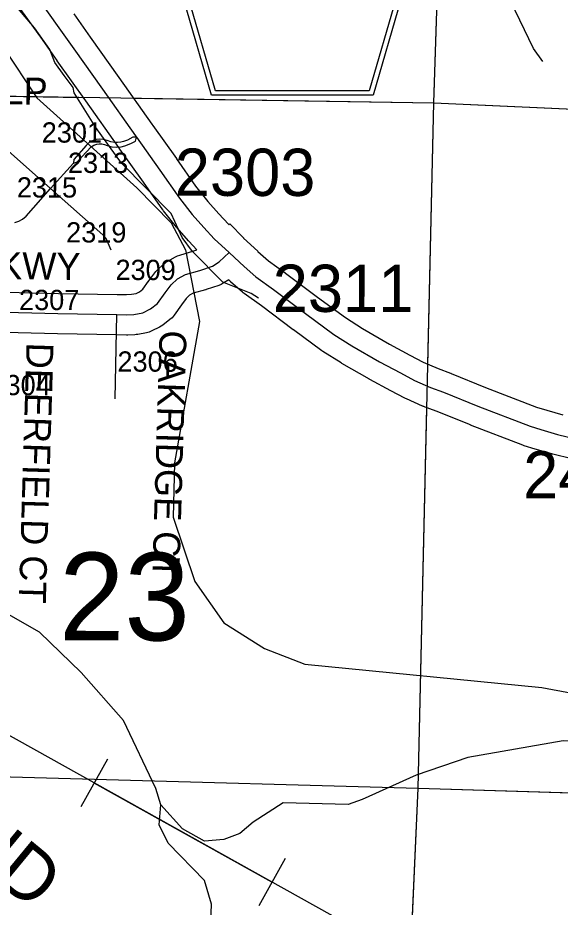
# Model space of a CAD drawing. Extents: x -132.8 to -73.3, y -60 to -26.
# Drawn here: x -117.648 to -116.845, y -54.589 to -53.272 of the extents above; entities that cross this region are included whole.
import ezdxf

# ---------------------------------------------------------------- set-up
doc = ezdxf.new("R2010")
doc.units = 0
for name, color, linetype in [('tdCoDivCarto', 7, 'Continuous'), ('tdCoHydroRiver', 7, 'Continuous'), ('tdCoPipe', 7, 'Continuous'), ('tdCoRRCL', 7, 'Continuous'), ('tdCoSecDivCarto', 7, 'Continuous'), ('tdCoSecRdNmbr', 7, 'Continuous'), ('tdCoSecRdTxt', 7, 'Continuous'), ('tdCoSecRteBand', 7, 'Continuous'), ('tdCoSecRteCL', 7, 'Continuous'), ('tdCoSectLine', 7, 'Continuous'), ('tdCoSectLinePart', 7, 'Continuous'), ('tdCoSectNmbr', 7, 'Continuous'), ('tdCoShieldCoRteHrd', 7, 'Continuous'), ('tdCoSurfAsphalt', 7, 'Continuous'), ('tdCoSurfConc', 7, 'Continuous'), ('tdCoSurfConcUnbanded', 7, 'Continuous')]:
    doc.layers.add(name, color=color, linetype=linetype)

msp = doc.modelspace()

# ---------------------------------------------------------------- linework, layer by layer
at = {"layer": 'tdCoDivCarto'}
for p, q in [((-117.5658, -53.4871), (-117.5657, -53.4871)), ((-117.5657, -53.4871), (-117.5654, -53.487))]:
    msp.add_line(p, q, dxfattribs=at)
for points in [[(-117.4725, -53.4488), (-117.4776, -53.4485), (-117.4858, -53.453), (-117.4916, -53.4551), (-117.4956, -53.456), (-117.5003, -53.4564), (-117.5051, -53.4564), (-117.5105, -53.4554), (-117.5157, -53.4535), (-117.5212, -53.452), (-117.5273, -53.4516), (-117.5319, -53.4522), (-117.5366, -53.4535), (-117.5418, -53.456), (-117.5471, -53.4608), (-117.5651, -53.4816), (-117.5658, -53.4871)], [(-117.5654, -53.487), (-117.5604, -53.4853), (-117.5396, -53.4629), (-117.5354, -53.4604), (-117.5311, -53.4588), (-117.5276, -53.4583), (-117.5235, -53.4586), (-117.5198, -53.4595), (-117.5157, -53.4609), (-117.5089, -53.4627), (-117.5022, -53.4632), (-117.4949, -53.4628), (-117.4895, -53.4616), (-117.4808, -53.4582), (-117.4739, -53.4543), (-117.4725, -53.4488)]]:
    msp.add_lwpolyline(points, dxfattribs=at)
at = {"layer": 'tdCoHydroRiver'}
for points in [[(-116.8707, -53.3366), (-116.8844, -53.3173), (-116.9249, -53.2327)], [(-117.2918, -53.6868), (-117.3027, -53.6802), (-117.3448, -53.6633), (-117.3894, -53.6179), (-117.4046, -53.597), (-117.421, -53.5618), (-117.4948, -53.4873), (-117.5328, -53.4342), (-117.5646, -53.3828), (-117.566, -53.3749), (-117.5797, -53.3572), (-117.5934, -53.3379), (-117.6008, -53.3188), (-117.6236, -53.2866), (-117.6481, -53.2575)], [(-117.4366, -54.4371), (-117.4438, -54.4133), (-117.4916, -54.3126), (-117.5545, -54.2414), (-117.616, -54.1814), (-117.6689, -54.1516), (-117.8063, -54.0974), (-117.9586, -54.0665), (-118.0751, -54.0539), (-118.1447, -54.0599), (-118.244, -54.114), (-118.2987, -54.152), (-118.3739, -54.1894), (-118.4117, -54.1884), (-118.4729, -54.1741), (-118.557, -54.1892), (-118.5885, -54.1868), (-118.6135, -54.1798), (-118.6484, -54.1836), (-118.6691, -54.1925), (-118.7064, -54.2294), (-118.8548, -54.2285)], [(-116.6489, -54.5492), (-116.6502, -54.5382), (-116.6548, -54.5349), (-116.6677, -54.4809), (-116.6997, -54.4359), (-116.7766, -54.3582), (-116.8062, -54.3433), (-116.8409, -54.3424), (-116.982, -54.3672), (-117.0585, -54.3936), (-117.1383, -54.4295), (-117.159, -54.4368), (-117.2551, -54.4342)], [(-117.2551, -54.4342), (-117.2999, -54.4629), (-117.3193, -54.4797), (-117.3432, -54.4885), (-117.3717, -54.4909), (-117.4044, -54.4727), (-117.4366, -54.4371)], [(-117.3094, -55.4046), (-117.3381, -55.3565), (-117.3421, -55.3296), (-117.3396, -55.2949), (-117.3343, -55.2745), (-117.3292, -55.2021), (-117.3362, -55.1672), (-117.3422, -55.156), (-117.3509, -55.1289), (-117.3498, -55.0296), (-117.3542, -55.0168), (-117.3624, -54.9093), (-117.3589, -54.6601), (-117.3627, -54.6253), (-117.3616, -54.5843), (-117.3717, -54.5493), (-117.4255, -54.4942), (-117.439, -54.467), (-117.4366, -54.4371)]]:
    msp.add_lwpolyline(points, dxfattribs=at)
at = {"layer": 'tdCoPipe'}
for p, q in [((-117.5153, -54.3699), (-117.5546, -54.4403)), ((-117.2521, -54.5167), (-117.2913, -54.587))]:
    msp.add_line(p, q, dxfattribs=at)
for points in [[(-115.7327, -56.7093), (-116.3792, -55.5939), (-116.7637, -54.8353), (-118.1151, -54.0815), (-118.6092, -53.8056), (-119.7966, -53.496), (-120.031, -53.2709)], [(-117.2718, -54.5519), (-117.535, -54.4051)]]:
    msp.add_lwpolyline(points, dxfattribs=at)
at = {"layer": 'tdCoRRCL'}
msp.add_lwpolyline([(-117.7743, -53.0804), (-117.6699, -53.3151), (-117.6198, -53.3905), (-117.4718, -53.5238), (-117.421, -53.5756), (-117.4, -53.6156), (-117.379, -53.7218), (-117.416, -53.9307), (-117.4181, -54.0111), (-117.3859, -54.1067), (-117.3433, -54.1677), (-117.2827, -54.2056), (-117.2233, -54.2292), (-116.8722, -54.2637), (-116.7827, -54.2802), (-116.7328, -54.3036), (-116.6616, -54.3591), (-116.6342, -54.3961), (-116.621, -54.4343), (-116.6103, -54.5119)], dxfattribs=at)
at = {"layer": 'tdCoSecDivCarto'}
for p, q in [((-117.4776, -53.4485), (-117.4858, -53.453)), ((-117.4725, -53.4488), (-117.4776, -53.4485)), ((-117.4739, -53.4543), (-117.4725, -53.4488)), ((-117.5471, -53.4608), (-117.5651, -53.4816)), ((-117.5418, -53.456), (-117.5471, -53.4608)), ((-117.5366, -53.4535), (-117.5418, -53.456)), ((-117.5396, -53.4629), (-117.5354, -53.4604)), ((-117.5319, -53.4522), (-117.5366, -53.4535)), ((-117.5354, -53.4604), (-117.5311, -53.4588)), ((-117.5273, -53.4516), (-117.5319, -53.4522)), ((-117.5311, -53.4588), (-117.5276, -53.4583)), ((-117.5276, -53.4583), (-117.5235, -53.4586)), ((-117.5212, -53.452), (-117.5273, -53.4516)), ((-117.5235, -53.4586), (-117.5198, -53.4595)), ((-117.5157, -53.4535), (-117.5212, -53.452)), ((-117.5198, -53.4595), (-117.5157, -53.4609)), ((-117.5105, -53.4554), (-117.5157, -53.4535)), ((-117.5157, -53.4609), (-117.5089, -53.4627)), ((-117.5051, -53.4564), (-117.5105, -53.4554)), ((-117.5003, -53.4564), (-117.5051, -53.4564)), ((-117.4956, -53.456), (-117.5003, -53.4564)), ((-117.4916, -53.4551), (-117.4956, -53.456)), ((-117.4949, -53.4628), (-117.4895, -53.4616)), ((-117.4858, -53.453), (-117.4916, -53.4551)), ((-117.4895, -53.4616), (-117.4808, -53.4582)), ((-117.4808, -53.4582), (-117.4739, -53.4543)), ((-117.5604, -53.4853), (-117.5396, -53.4629)), ((-117.5089, -53.4627), (-117.5022, -53.4632)), ((-117.5022, -53.4632), (-117.4949, -53.4628)), ((-117.5651, -53.4816), (-117.5658, -53.4871)), ((-117.5658, -53.4871), (-117.5657, -53.4871)), ((-117.5657, -53.4871), (-117.5654, -53.487)), ((-117.5654, -53.487), (-117.5604, -53.4853))]:
    msp.add_line(p, q, dxfattribs=at)
at = {"layer": 'tdCoSecRteBand'}
for points in [[(-117.6855, -53.6774), (-117.588, -53.6799), (-117.501, -53.6814), (-117.4872, -53.6816), (-117.4797, -53.6813), (-117.4728, -53.68), (-117.4678, -53.6775), (-117.463, -53.6738), (-117.4545, -53.6619), (-117.4543, -53.6616), (-117.4541, -53.6613), (-117.4452, -53.6495), (-117.4437, -53.6475), (-117.4419, -53.6457), (-117.4322, -53.6366), (-117.4295, -53.634), (-117.4261, -53.6321), (-117.4145, -53.6257), (-117.4116, -53.6241), (-117.4084, -53.6232), (-117.3877, -53.6171), (-117.3829, -53.6156), (-117.3948, -53.6027), (-117.395, -53.6025), (-117.3952, -53.6023), (-117.4123, -53.5829), (-117.4128, -53.5823), (-117.4133, -53.5817), (-117.4324, -53.5577), (-117.433, -53.5569), (-117.4335, -53.5562), (-117.4622, -53.515), (-117.4969, -53.4662), (-117.4984, -53.464), (-117.4985, -53.464), (-117.4985, -53.464), (-117.5474, -53.3948), (-117.5898, -53.3355), (-117.5899, -53.3353), (-117.59, -53.3352), (-117.6142, -53.3004), (-117.6603, -53.2358)], [(-117.5651, -53.266), (-117.5409, -53.3007), (-117.4985, -53.36), (-117.4984, -53.3601), (-117.4984, -53.3601), (-117.4495, -53.4293), (-117.448, -53.4314), (-117.4133, -53.4804), (-117.4132, -53.4805), (-117.4131, -53.4806), (-117.3848, -53.5211), (-117.3668, -53.5438), (-117.3504, -53.5623), (-117.3364, -53.5776), (-117.3356, -53.5783), (-117.3341, -53.5769), (-117.3142, -53.5979), (-117.3141, -53.598), (-117.3141, -53.598), (-117.2928, -53.6174), (-117.2931, -53.6177), (-117.293, -53.6178), (-117.277, -53.6319), (-117.2522, -53.6497), (-117.2519, -53.6499), (-117.2516, -53.6501), (-117.2045, -53.6857), (-117.1631, -53.7158), (-117.1378, -53.7321), (-117.098, -53.755), (-117.0676, -53.7713), (-117.0479, -53.7817), (-117.0257, -53.7914), (-117.0075, -53.7981), (-117.0071, -53.7983), (-117.0067, -53.7985), (-116.9558, -53.8191), (-116.88, -53.8485), (-116.8651, -53.8529), (-116.8412, -53.86)], [(-116.8278, -53.9251), (-116.8562, -53.9181), (-116.8568, -53.9179), (-116.8575, -53.9177), (-116.8822, -53.9105), (-116.8823, -53.9104), (-116.8824, -53.9104), (-116.8984, -53.9056), (-116.8995, -53.9052), (-116.9006, -53.9048), (-116.9777, -53.8749), (-116.9779, -53.8748), (-116.9781, -53.8748), (-117.0288, -53.8542), (-117.0474, -53.8474), (-117.0482, -53.8471), (-117.049, -53.8467), (-117.0729, -53.8362), (-117.074, -53.8358), (-117.0749, -53.8353), (-117.0957, -53.8243), (-117.0958, -53.8242), (-117.0959, -53.8242), (-117.1268, -53.8076), (-117.1272, -53.8074), (-117.1275, -53.8072), (-117.1683, -53.7837), (-117.169, -53.7834), (-117.1696, -53.783), (-117.1963, -53.7659), (-117.197, -53.7654), (-117.1978, -53.7649), (-117.2401, -53.734), (-117.2403, -53.7339), (-117.2405, -53.7337), (-117.2874, -53.6982), (-117.3131, -53.6799), (-117.3143, -53.679), (-117.3154, -53.678), (-117.333, -53.6626), (-117.3334, -53.6622), (-117.3338, -53.6619), (-117.3359, -53.6599), (-117.344, -53.665), (-117.3471, -53.667), (-117.3507, -53.6681), (-117.3694, -53.6743), (-117.3699, -53.6745), (-117.3704, -53.6746), (-117.3884, -53.6798), (-117.3937, -53.6828), (-117.3987, -53.6875), (-117.4059, -53.6971), (-117.4168, -53.7123), (-117.4194, -53.716), (-117.4229, -53.7187), (-117.4335, -53.7268), (-117.4358, -53.7286), (-117.4384, -53.7299), (-117.4497, -53.7355), (-117.4535, -53.7374), (-117.4576, -53.7382), (-117.4706, -53.7406), (-117.4727, -53.741), (-117.4748, -53.7411), (-117.4854, -53.7416), (-117.4864, -53.7417), (-117.4873, -53.7416), (-117.502, -53.7414), (-117.5892, -53.7399), (-117.5893, -53.7399), (-117.5894, -53.7399), (-117.687, -53.7374)]]:
    msp.add_lwpolyline(points, dxfattribs=at)
at = {"layer": 'tdCoSecRteCL'}
for p, q in [((-117.5995, -53.5245), (-117.5658, -53.4871)), ((-117.504, -53.8362), (-117.5015, -53.7114))]:
    msp.add_line(p, q, dxfattribs=at)
for points in [[(-118.338, -52.7262), (-118.2743, -52.753), (-118.2436, -52.7666), (-118.1841, -52.7924), (-118.1223, -52.8219), (-118.069, -52.8495), (-118.0022, -52.8856), (-117.937, -52.9205), (-117.8789, -52.9515), (-117.842, -52.9712), (-117.822, -52.9834), (-117.8084, -52.993), (-117.7978, -53.002), (-117.7849, -53.0143), (-117.7727, -53.029), (-117.7529, -53.0555), (-117.7258, -53.0929), (-117.69, -53.1429), (-117.6359, -53.2183), (-117.5897, -53.2831), (-117.5654, -53.318), (-117.5229, -53.3774), (-117.474, -53.4467), (-117.4725, -53.4488)], [(-117.4725, -53.4488), (-117.4776, -53.4485), (-117.4858, -53.453), (-117.4916, -53.4551), (-117.4956, -53.456), (-117.5003, -53.4564), (-117.5051, -53.4564), (-117.5105, -53.4554), (-117.5157, -53.4535), (-117.5212, -53.452), (-117.5273, -53.4516), (-117.5319, -53.4522), (-117.5366, -53.4535), (-117.5418, -53.456), (-117.5471, -53.4608), (-117.5651, -53.4816), (-117.5658, -53.4871)], [(-117.5658, -53.4871), (-117.5657, -53.4871), (-117.5654, -53.487), (-117.5604, -53.4853), (-117.5396, -53.4629), (-117.5354, -53.4604), (-117.5311, -53.4588), (-117.5276, -53.4583), (-117.5235, -53.4586), (-117.5198, -53.4595), (-117.5157, -53.4609), (-117.5089, -53.4627), (-117.5022, -53.4632), (-117.4949, -53.4628), (-117.4895, -53.4616), (-117.4808, -53.4582), (-117.4739, -53.4543), (-117.4725, -53.4488)], [(-117.4725, -53.4488), (-117.4377, -53.4977), (-117.4089, -53.539), (-117.3898, -53.5631), (-117.3727, -53.5824), (-117.3576, -53.5989), (-117.3352, -53.6193)], [(-117.5995, -53.5245), (-117.6668, -53.465)], [(-117.6526, -53.5751), (-117.6467, -53.5729), (-117.6412, -53.57), (-117.6357, -53.5655), (-117.5995, -53.5245)], [(-117.5098, -53.6157), (-117.5173, -53.5987), (-117.5223, -53.593), (-117.5995, -53.5245)], [(-117.5015, -53.7114), (-117.4868, -53.7117), (-117.4762, -53.7112), (-117.4631, -53.7087), (-117.4518, -53.703), (-117.4412, -53.6949), (-117.4301, -53.6793), (-117.4212, -53.6675), (-117.4116, -53.6584), (-117.4, -53.652), (-117.3788, -53.6458), (-117.3601, -53.6396), (-117.3499, -53.6332), (-117.3352, -53.6193)], [(-117.3352, -53.6193), (-117.3345, -53.6199), (-117.3132, -53.64), (-117.2956, -53.6555), (-117.2697, -53.6741), (-117.2224, -53.7098), (-117.1801, -53.7406), (-117.1534, -53.7577), (-117.1126, -53.7812), (-117.0817, -53.7978), (-117.0609, -53.8088), (-117.037, -53.8192), (-117.0179, -53.8263), (-116.9668, -53.8469), (-116.8898, -53.8768), (-116.8737, -53.8817), (-116.849, -53.889), (-116.8206, -53.896)], [(-117.6863, -53.7074), (-117.5887, -53.7099), (-117.5015, -53.7114)]]:
    msp.add_lwpolyline(points, dxfattribs=at)
at = {"layer": 'tdCoSectLine'}
for points in [[(-117.0322, -53.3979), (-116.9995, -52.4001)], [(-118.0219, -53.382), (-117.0322, -53.3979)], [(-117.0554, -54.4124), (-117.0322, -53.3979)], [(-117.0322, -53.3979), (-116.042, -53.4425)], [(-118.0496, -54.385), (-117.0554, -54.4124)], [(-117.0994, -55.4066), (-117.0554, -54.4124)], [(-117.0554, -54.4124), (-116.0724, -54.4424)]]:
    msp.add_lwpolyline(points, dxfattribs=at)
at = {"layer": 'tdCoSectLinePart'}
for points in [[(-117.0322, -53.3979), (-117.0004, -52.4272)], [(-118.0219, -53.382), (-117.5517, -53.3896)], [(-117.4773, -53.3908), (-117.0322, -53.3979)], [(-117.0411, -53.7849), (-117.0322, -53.3979)], [(-117.0322, -53.3979), (-116.0715, -53.4412)], [(-117.0554, -54.4124), (-117.0426, -53.8494)], [(-118.0496, -54.385), (-117.0554, -54.4124)], [(-117.0893, -55.1771), (-117.0554, -54.4124)], [(-117.0554, -54.4124), (-116.6025, -54.4263)]]:
    msp.add_lwpolyline(points, dxfattribs=at)
at = {"layer": 'tdCoShieldCoRteHrd'}
for points in [[(-117.3615, -53.3865), (-117.4434, -53.1036), (-117.4473, -53.0905), (-117.448, -53.0846), (-117.448, -53.0768), (-117.4438, -53.0665), (-117.4365, -53.058), (-117.4269, -53.0513), (-117.2596, -52.979), (-117.2521, -52.9773), (-117.2417, -52.9764), (-117.2313, -52.9773), (-117.2238, -52.979), (-117.0565, -53.0513), (-117.0469, -53.058), (-117.0396, -53.0665), (-117.0354, -53.0768), (-117.0354, -53.0846), (-117.0361, -53.0905), (-117.04, -53.1036), (-117.1219, -53.3865)], [(-117.3556, -53.3802), (-117.4353, -53.1049), (-117.4391, -53.0923), (-117.4398, -53.0866), (-117.4398, -53.0791), (-117.4357, -53.0692), (-117.4287, -53.0611), (-117.4195, -53.0547), (-117.2589, -52.9852), (-117.2517, -52.9837), (-117.2417, -52.9828), (-117.2317, -52.9837), (-117.2245, -52.9852), (-117.0639, -53.0547), (-117.0547, -53.0611), (-117.0477, -53.0692), (-117.0437, -53.0791), (-117.0437, -53.0866), (-117.0444, -53.0923), (-117.0481, -53.1049), (-117.1278, -53.3802)]]:
    msp.add_lwpolyline(points, close=True, dxfattribs=at)
at = {"layer": 'tdCoSurfAsphalt'}
msp.add_lwpolyline([(-117.6359, -53.2183), (-117.5897, -53.2831), (-117.5654, -53.318), (-117.5229, -53.3774), (-117.474, -53.4467), (-117.4725, -53.4488), (-117.4377, -53.4977), (-117.4089, -53.539), (-117.3898, -53.5631), (-117.3727, -53.5824), (-117.3576, -53.5989), (-117.3352, -53.6193), (-117.3345, -53.6199), (-117.3132, -53.64), (-117.2956, -53.6555), (-117.2697, -53.6741), (-117.2224, -53.7098), (-117.1801, -53.7406), (-117.1534, -53.7577), (-117.1126, -53.7812), (-117.0817, -53.7978), (-117.0609, -53.8088), (-117.037, -53.8192), (-117.0179, -53.8263), (-116.9668, -53.8469), (-116.8898, -53.8768), (-116.8737, -53.8817), (-116.849, -53.889), (-116.8206, -53.896)], dxfattribs=at)
at = {"layer": 'tdCoSurfConc'}
msp.add_lwpolyline([(-117.6863, -53.7074), (-117.5887, -53.7099), (-117.5015, -53.7114), (-117.4868, -53.7117), (-117.4762, -53.7112), (-117.4631, -53.7087), (-117.4518, -53.703), (-117.4412, -53.6949), (-117.4301, -53.6793), (-117.4212, -53.6675), (-117.4116, -53.6584), (-117.4, -53.652), (-117.3788, -53.6458), (-117.3601, -53.6396), (-117.3499, -53.6332), (-117.3352, -53.6193)], dxfattribs=at)
at = {"layer": 'tdCoSurfConcUnbanded'}
for p, q in [((-117.5995, -53.5245), (-117.5658, -53.4871)), ((-117.504, -53.8362), (-117.5015, -53.7114))]:
    msp.add_line(p, q, dxfattribs=at)
for points in [[(-117.5658, -53.4871), (-117.5657, -53.4871), (-117.5654, -53.487), (-117.5604, -53.4853), (-117.5396, -53.4629), (-117.5354, -53.4604), (-117.5311, -53.4588), (-117.5276, -53.4583), (-117.5235, -53.4586), (-117.5198, -53.4595), (-117.5157, -53.4609), (-117.5089, -53.4627), (-117.5022, -53.4632), (-117.4949, -53.4628), (-117.4895, -53.4616), (-117.4808, -53.4582), (-117.4739, -53.4543), (-117.4725, -53.4488), (-117.4776, -53.4485), (-117.4858, -53.453), (-117.4916, -53.4551), (-117.4956, -53.456), (-117.5003, -53.4564), (-117.5051, -53.4564), (-117.5105, -53.4554), (-117.5157, -53.4535), (-117.5212, -53.452), (-117.5273, -53.4516), (-117.5319, -53.4522), (-117.5366, -53.4535), (-117.5418, -53.456), (-117.5471, -53.4608), (-117.5651, -53.4816), (-117.5658, -53.4871)], [(-117.5995, -53.5245), (-117.6668, -53.465)], [(-117.6526, -53.5751), (-117.6467, -53.5729), (-117.6412, -53.57), (-117.6357, -53.5655), (-117.5995, -53.5245)], [(-117.5098, -53.6157), (-117.5173, -53.5987), (-117.5223, -53.593), (-117.5995, -53.5245)]]:
    msp.add_lwpolyline(points, dxfattribs=at)

# ---------------------------------------------------------------- texts
at = {"layer": 'tdCoSecRdNmbr'}
for s, height, rotation, p in [('2301', 0.03, 359.9124, (-117.6127, -53.4566)), ('2313', 0.03, 359.9124, (-117.5739, -53.5015)), ('2303', 0.07, 359.9123, (-117.4158, -53.5354)), ('2315', 0.03, 359.9124, (-117.6496, -53.5379)), ('2319', 0.03, 359.9124, (-117.5766, -53.6045)), ('2309', 0.03, 359.9124, (-117.5035, -53.6601)), ('2311', 0.07, 359.912, (-117.2708, -53.7073)), ('2307', 0.03, 359.9123, (-117.6463, -53.7046)), ('2306', 0.03, 359.9125, (-117.5006, -53.7958)), ('2304', 0.03, 359.9123, (-117.6886, -53.8306)), ('2403', 0.07, 359.9121, (-116.9, -53.9835))]:
    msp.add_text(s, height=height, rotation=rotation, dxfattribs=at).set_placement(p)
at = {"layer": 'tdCoSecRdTxt'}
for s, height, rotation, p in [('TRACE VIEW LP', 0.04, 359.2673, (-118.0172, -53.3954)), ('MEADOWVIEW PKWY', 0.04, 359.2673, (-118.1113, -53.653)), ('OAKRIDGE CT', 0.04, 268.2848, (-117.4381, -53.7344)), ('DEERFIELD CT', 0.04, 268.2846, (-117.6351, -53.7524)), ('WOODLAND', 0.08, 320.4911, (-118.112, -54.195))]:
    msp.add_text(s, height=height, rotation=rotation, dxfattribs=at).set_placement(p)
at = {"layer": 'tdCoSectNmbr'}
msp.add_text('23', height=0.13, rotation=359.9124, dxfattribs=at).set_placement((-117.587, -54.1937))

doc.saveas('drawing.dxf')
